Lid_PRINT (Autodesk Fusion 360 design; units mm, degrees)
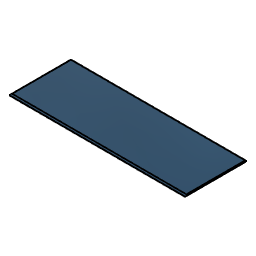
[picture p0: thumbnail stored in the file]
sketch "Sketch1" plane through (0, 0, 0) normal (0, 0, 1) x axis (1, 0, 0)
  line L1 (232.6, 0) -> (0, 0)
  line L2 (232.6, 81.6) -> (232.6, 0)
  line L3 (0, 81.6) -> (232.6, 81.6)
  line L4 (0, 0) -> (0, 81.6)
  line L5 (231.4, 80.4) -> (1.2, 80.4)
  line L6 (231.4, 3) -> (231.4, 80.4)
  line L7 (1.2, 3) -> (231.4, 3)
  line L8 (1.2, 80.4) -> (1.2, 3)
  point P1 (0, 0)
  point P2 (0, 0)
  point P4 (232.6, 81.6)
  point P5 (0, 81.6)
  horizontal L1
  vertical L2
  horizontal L3
  vertical L4
  coincident P1 P2
  horizontal L5
  vertical L6
  horizontal L7
  vertical L8
  dimension "d1" distance L3 L5 = 1.2
  dimension "d2" distance L2 L6 = 1.2
  dimension "d3" distance L1 L7 = 3
  dimension "d4" distance L4 L8 = 1.2
  dimension "d5" distance P4 P5 = 232.6
  dimension "d10" distance P2 P5 = 81.6
extrude "Extrude1" new body sketch "Sketch1" along normal blind 0.8
extrude "Extrude2" add sketch "Sketch1" profile of L5 L6 L7 L8 along normal blind 1.3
